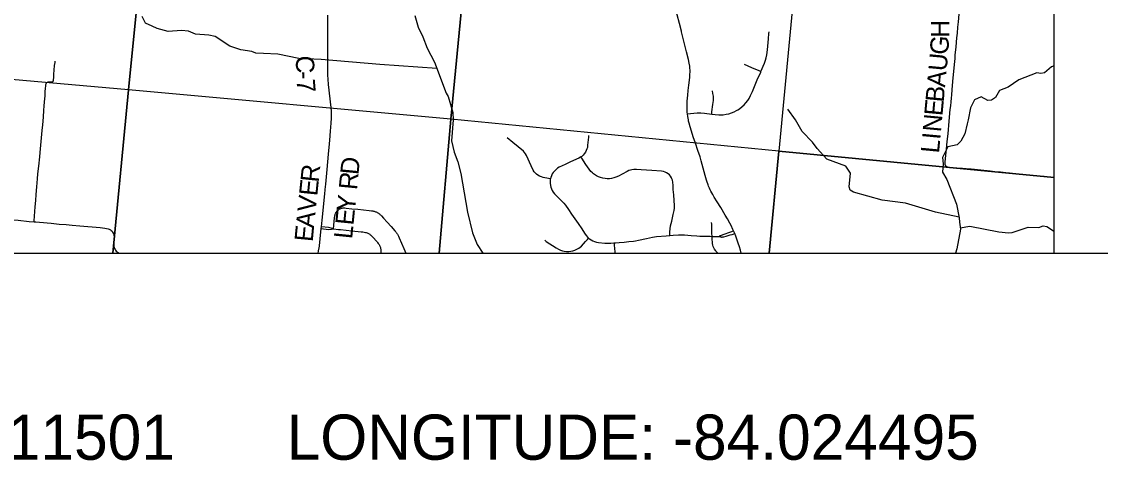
# Model space of a CAD drawing. Extents: x -1.4 to 35.4, y 0 to 22.
# Drawn here: x 28.091 to 31.432, y 12.413 to 13.771 of the extents above; entities that cross this region are included whole.
import ezdxf

# ---------------------------------------------------------------- set-up
doc = ezdxf.new("R2010")
doc.units = 0
for name, color, linetype in [('GM_X_City_Street', 7, 'Continuous'), ('GM_X_County_Road', 7, 'Continuous'), ('GM_X_County_Road_Text', 7, 'Continuous'), ('GM_X_Minor_River', 7, 'Continuous'), ('GM_X_Section', 7, 'Continuous'), ('GM_X_Township_Road', 7, 'Continuous'), ('GM_X_Township_Road_Text', 7, 'Continuous'), ('SC_Scratch1', 7, 'Continuous'), ('SH_Border', 7, 'Continuous'), ('SH_Cut_Line', 7, 'Continuous'), ('SH_Text', 7, 'Continuous')]:
    doc.layers.add(name, color=color, linetype=linetype)

msp = doc.modelspace()

# ---------------------------------------------------------------- linework, layer by layer
at = {"layer": 'GM_X_City_Street'}
msp.add_lwpolyline([(28.1301, 13.1513), (28.1304, 13.1548), (28.1337, 13.1978), (28.135, 13.2176), (28.1364, 13.236), (28.1385, 13.2592), (28.1408, 13.2848), (28.142, 13.2997), (28.1443, 13.3232), (28.1474, 13.3528), (28.1488, 13.3664), (28.1527, 13.411), (28.155, 13.4345), (28.1567, 13.4512), (28.1588, 13.4754), (28.1604, 13.4971), (28.1613, 13.5095), (28.1624, 13.5224), (28.1639, 13.541), (28.1647, 13.5534), (28.1656, 13.565), (28.1661, 13.5711), (28.1668, 13.5767), (28.1671, 13.5782), (28.1675, 13.5794), (28.168, 13.5805), (28.1689, 13.5818), (28.1699, 13.5827), (28.1713, 13.5835), (28.1726, 13.5841), (28.1739, 13.5846), (28.1747, 13.5848), (28.1765, 13.585), (28.1796, 13.5847), (28.1839, 13.5842), (28.1857, 13.5842), (28.1867, 13.5844), (28.1876, 13.5849), (28.1886, 13.586), (28.1893, 13.5874), (28.1897, 13.5887), (28.1902, 13.5924), (28.1907, 13.5973), (28.1914, 13.6104), (28.1919, 13.619), (28.1924, 13.6264), (28.1928, 13.6301), (28.1934, 13.635), (28.195, 13.6448), (28.1957, 13.649)], dxfattribs=at)
at = {"layer": 'GM_X_County_Road'}
for points in [[(31.2897, 13.2886), (31.2897, 14.2937), (30.5317, 14.3711), (30.4366, 13.3703)], [(27.3311, 13.0546), (28.3737, 13.0546), (28.4224, 13.5597), (27.3811, 13.6516)], [(28.3737, 13.0546), (29.3843, 13.0546), (29.4209, 13.4686), (28.4224, 13.5597)], [(29.3843, 13.0546), (30.4062, 13.0546), (30.4366, 13.3703), (29.4209, 13.4686)], [(30.4062, 13.0546), (31.2897, 13.0546), (31.2897, 13.2886), (30.4366, 13.3703)]]:
    msp.add_lwpolyline(points, close=True, dxfattribs=at)
for points in [[(30.1352, 13.7394), (30.1347, 13.7413), (30.1285, 13.7653), (30.1215, 13.7922), (30.1144, 13.8199), (30.1084, 13.8432)], [(29.0125, 13.0701), (29.0136, 13.0773), (29.0161, 13.0983), (29.0192, 13.1304), (29.0197, 13.1362), (29.0219, 13.1564), (29.0273, 13.2065), (29.0307, 13.2392), (29.0318, 13.2491), (29.0319, 13.2509), (29.0335, 13.2676), (29.0376, 13.3128), (29.042, 13.3604), (29.0448, 13.3926), (29.0456, 13.4044), (29.0479, 13.4323), (29.0498, 13.4564), (29.0507, 13.4726), (29.0509, 13.4838), (29.0506, 13.4938), (29.0498, 13.505), (29.0422, 13.5766), (29.0407, 13.5927), (29.04, 13.6057), (29.0396, 13.6212), (29.0399, 13.6535), (29.0399, 13.6777), (29.04, 13.705), (29.04, 13.7473), (29.0401, 13.7908)], [(30.1535, 13.4853), (30.1531, 13.4898), (30.1529, 13.4932), (30.1527, 13.4975), (30.1526, 13.5022), (30.1526, 13.5086), (30.1527, 13.5138), (30.1531, 13.525), (30.1543, 13.543), (30.1557, 13.5575), (30.1576, 13.5741), (30.1604, 13.5986), (30.1609, 13.6042), (30.1612, 13.6091), (30.1614, 13.614), (30.1614, 13.6184), (30.1615, 13.6222), (30.1613, 13.6258), (30.161, 13.6296), (30.1605, 13.6331), (30.159, 13.6422), (30.1563, 13.6543), (30.1506, 13.6778), (30.1434, 13.7061), (30.1352, 13.7394)], [(30.2998, 13.1151), (30.2983, 13.119), (30.2965, 13.1231), (30.2945, 13.1275), (30.2886, 13.1398), (30.2851, 13.147), (30.2772, 13.161), (30.2706, 13.1723), (30.2567, 13.1951), (30.2452, 13.2135), (30.2367, 13.2273), (30.2318, 13.2359), (30.2263, 13.2457), (30.2241, 13.2502), (30.2217, 13.2553), (30.219, 13.2614), (30.2174, 13.2654), (30.2161, 13.2692), (30.2145, 13.2742), (30.2128, 13.2798), (30.2087, 13.2942), (30.2056, 13.3057), (30.1963, 13.3398), (30.1924, 13.3529), (30.1861, 13.3724), (30.1781, 13.3953), (30.1714, 13.414), (30.1656, 13.4317), (30.1614, 13.4454), (30.1584, 13.4569), (30.1571, 13.4624), (30.1562, 13.4672), (30.1545, 13.4771), (30.1535, 13.4853)], [(27.8712, 13.1683), (27.8731, 13.1695), (27.876, 13.1709), (27.8797, 13.172), (27.8835, 13.1727), (27.8867, 13.1729), (27.8917, 13.1727), (27.9177, 13.1707), (27.9258, 13.17), (27.9406, 13.1687), (27.9623, 13.1668), (27.9802, 13.165), (27.9987, 13.1634), (28.0229, 13.1611), (28.0321, 13.1603), (28.0389, 13.1597), (28.0544, 13.1583), (28.0804, 13.1559), (28.1144, 13.1527), (28.1301, 13.1513)], [(28.1301, 13.1513), (28.1354, 13.1509), (28.1701, 13.1478), (28.1824, 13.1467), (28.1991, 13.1452), (28.2072, 13.1445), (28.2294, 13.1425), (28.248, 13.1409), (28.2721, 13.1388), (28.3346, 13.1332), (28.3489, 13.1317), (28.3545, 13.1308), (28.3594, 13.1296), (28.3624, 13.1285), (28.367, 13.1261), (28.3691, 13.1246), (28.3714, 13.1223), (28.3733, 13.1197), (28.3752, 13.1164), (28.3765, 13.1135), (28.3774, 13.1103), (28.3779, 13.1065), (28.3779, 13.1002), (28.3773, 13.0915), (28.3769, 13.0853), (28.3769, 13.0792), (28.3774, 13.0744), (28.3779, 13.072), (28.379, 13.0686), (28.3806, 13.0654), (28.3818, 13.0634), (28.3842, 13.0607), (28.3874, 13.058), (28.3905, 13.0562), (28.3939, 13.0546)], [(30.3197, 13.0546), (30.3174, 13.0633), (30.3143, 13.074), (30.3108, 13.0847), (30.3052, 13.1011), (30.303, 13.1069), (30.2998, 13.1151)], [(29.0094, 13.0546), (29.0109, 13.0607), (29.0122, 13.0681), (29.0125, 13.0701)]]:
    msp.add_lwpolyline(points, dxfattribs=at)
at = {"layer": 'GM_X_Minor_River'}
for points in [[(29.3777, 13.6255), (29.2005, 13.638), (29.0187, 13.6539), (28.9497, 13.6568), (28.8847, 13.6699), (28.84, 13.6727), (28.8165, 13.6731), (28.8041, 13.6783), (28.7704, 13.6836), (28.7358, 13.6953), (28.6908, 13.7246), (28.6708, 13.7289), (28.6299, 13.732), (28.6085, 13.7411), (28.5861, 13.7435), (28.5451, 13.7401), (28.5115, 13.7503), (28.4961, 13.7574), (28.4747, 13.7666), (28.4652, 13.7869)], [(29.3093, 13.7899), (29.3192, 13.754), (29.3338, 13.7238), (29.3475, 13.6886), (29.3702, 13.6452), (29.4066, 13.5492), (29.4121, 13.5396), (29.427, 13.4896), (29.428, 13.4672), (29.423, 13.402), (29.4306, 13.3673), (29.4425, 13.3367), (29.452, 13.3004), (29.472, 13.1808), (29.4874, 13.1175)], [(31.2897, 13.6344), (31.2811, 13.6311), (31.2596, 13.6129), (31.2478, 13.6105), (31.2353, 13.6123), (31.1793, 13.5907), (31.147, 13.5686), (31.1203, 13.5578), (31.1074, 13.5357), (31.0955, 13.5284), (31.0841, 13.5264), (31.0635, 13.5378), (31.0429, 13.5287), (31.0303, 13.504), (31.0224, 13.467), (31.0195, 13.4549), (31.0121, 13.4236), (30.9999, 13.4007), (30.9891, 13.3899), (30.9602, 13.3833), (30.9433, 13.3507), (30.9452, 13.331), (30.9436, 13.3052), (30.9567, 13.2822), (30.9863, 13.2058), (30.9953, 13.1635), (30.9965, 13.1498), (30.9988, 13.1285), (30.9877, 13.0681), (30.9834, 13.0546)], [(30.9948, 13.1658), (30.9218, 13.1813), (30.8285, 13.2094), (30.7568, 13.2188), (30.6676, 13.2434), (30.6571, 13.2493), (30.6539, 13.2593), (30.6585, 13.3024), (30.6438, 13.3232), (30.5852, 13.3449), (30.5556, 13.3781), (30.5408, 13.3981), (30.5085, 13.4314), (30.4884, 13.4667), (30.4641, 13.5005)], [(30.9983, 13.1327), (31.0277, 13.1374), (31.1174, 13.1204), (31.148, 13.1175), (31.159, 13.1184), (31.2086, 13.1348), (31.2418, 13.1341), (31.2552, 13.1391), (31.2665, 13.1366), (31.287, 13.1233), (31.2897, 13.1225)], [(29.4874, 13.1175), (29.5023, 13.0815), (29.5199, 13.0546)]]:
    msp.add_lwpolyline(points, dxfattribs=at)
at = {"layer": 'GM_X_Section'}
for points in [[(28.5233, 14.5759), (28.4224, 13.5597), (27.3811, 13.6516), (27.481, 14.6746)], [(29.5182, 14.475), (29.4209, 13.4686), (28.4224, 13.5597), (28.5233, 14.5759)], [(29.5182, 14.475), (30.5317, 14.3711), (30.4366, 13.3703), (29.4209, 13.4686)]]:
    msp.add_lwpolyline(points, close=True, dxfattribs=at)
at = {"layer": 'GM_X_Township_Road'}
msp.add_line((29.0573, 13.1293), (29.0608, 13.1633), dxfattribs=at)
for points in [[(31.2897, 13.288), (31.2845, 13.2885), (31.2585, 13.2912), (31.24, 13.293), (31.2124, 13.2957), (31.1914, 13.2977), (31.1686, 13.3), (31.1513, 13.3017), (31.1398, 13.3028), (31.1226, 13.3047), (31.1053, 13.3065), (31.0914, 13.3079), (31.0626, 13.3107), (31.0321, 13.3139), (31.0167, 13.3153), (31.0053, 13.3163), (30.9873, 13.3177), (30.9766, 13.3185), (30.9655, 13.3195), (30.9624, 13.3199), (30.9602, 13.3203), (30.9591, 13.3206), (30.9582, 13.3209), (30.9573, 13.3213), (30.9565, 13.3217), (30.9556, 13.3224), (30.9548, 13.3229), (30.9542, 13.3235), (30.9537, 13.3242), (30.9533, 13.3249), (30.9529, 13.3256), (30.9525, 13.3263), (30.9522, 13.3271), (30.952, 13.328), (30.9518, 13.3291), (30.9516, 13.33), (30.9515, 13.3311), (30.9515, 13.3325), (30.9515, 13.3341), (30.9517, 13.3369), (30.9526, 13.3458), (30.9537, 13.3572), (30.9546, 13.3662), (30.9557, 13.3757), (30.9581, 13.4), (30.9605, 13.4242), (30.9643, 13.4631), (30.9674, 13.499), (30.9687, 13.5105), (30.9699, 13.5232), (30.9708, 13.5336), (30.9719, 13.5442), (30.9734, 13.5603), (30.9746, 13.573), (30.9767, 13.5973), (30.9784, 13.6169), (30.9804, 13.6387), (30.9821, 13.6572), (30.9831, 13.6679), (30.9855, 13.6916), (30.9869, 13.7079), (30.9881, 13.7211), (30.9894, 13.7349), (30.9912, 13.754), (30.9929, 13.7701), (30.9955, 13.7943)], [(30.381, 13.6166), (30.3921, 13.6424), (30.3957, 13.6522), (30.3976, 13.6593), (30.3991, 13.6678), (30.4009, 13.6838), (30.4043, 13.7178), (30.4059, 13.7345), (30.4064, 13.7397)], [(30.3288, 13.6395), (30.3522, 13.6291), (30.3744, 13.6195), (30.381, 13.6166)], [(30.2285, 13.4849), (30.239, 13.4836), (30.2507, 13.4826), (30.2581, 13.4826), (30.2636, 13.4827), (30.2733, 13.4843), (30.2817, 13.4861), (30.2899, 13.4887), (30.2985, 13.492), (30.3057, 13.4955), (30.3093, 13.4977), (30.3149, 13.5015), (30.3232, 13.5079), (30.329, 13.5134), (30.3344, 13.5193), (30.34, 13.5266), (30.3444, 13.5333), (30.3491, 13.542), (30.3549, 13.5549), (30.3611, 13.5699), (30.3697, 13.5905), (30.3803, 13.615), (30.381, 13.6166)], [(30.2285, 13.4849), (30.2294, 13.4917), (30.2323, 13.514), (30.2337, 13.5264), (30.234, 13.5344), (30.2338, 13.54), (30.2324, 13.5486), (30.2308, 13.5572)], [(30.1535, 13.4853), (30.1629, 13.4863), (30.1833, 13.4885), (30.1902, 13.4888), (30.1945, 13.4888), (30.2063, 13.4877), (30.2285, 13.4849)], [(29.729, 13.2841), (29.7234, 13.2852), (29.707, 13.2886), (29.7011, 13.2904), (29.6954, 13.2928), (29.69, 13.2959), (29.6855, 13.2992), (29.6819, 13.3026), (29.6787, 13.3064), (29.6757, 13.3111), (29.6692, 13.3245), (29.6549, 13.3569), (29.6521, 13.3617), (29.6492, 13.3657), (29.6453, 13.3697), (29.6127, 13.3965), (29.5954, 13.4109)], [(29.8471, 13.4187), (29.8466, 13.4134), (29.8444, 13.3886), (29.8434, 13.3818), (29.8421, 13.377), (29.8401, 13.3718), (29.8374, 13.3669), (29.8339, 13.3618), (29.8301, 13.3577), (29.826, 13.3539), (29.8233, 13.3521)], [(29.8233, 13.3521), (29.8219, 13.3511), (29.817, 13.3484), (29.7917, 13.3366), (29.7752, 13.3292), (29.7562, 13.32), (29.7514, 13.3171), (29.7464, 13.3134), (29.7424, 13.3095), (29.738, 13.3043), (29.7349, 13.2996), (29.7321, 13.294), (29.73, 13.2882), (29.729, 13.2841)], [(30.0988, 13.1092), (30.0987, 13.1161), (30.0986, 13.1206), (30.0996, 13.1293), (30.1013, 13.1385), (30.1049, 13.1537), (30.1096, 13.1736), (30.1123, 13.1862), (30.1133, 13.1935), (30.1132, 13.2008), (30.1111, 13.2348), (30.1097, 13.2515), (30.1088, 13.2639), (30.1079, 13.2744), (30.1069, 13.2798), (30.1054, 13.2844), (30.1039, 13.2876), (30.101, 13.2922), (30.0975, 13.2964), (30.0935, 13.3001), (30.089, 13.3032), (30.0847, 13.3052), (30.0795, 13.3068), (30.0735, 13.3078), (30.0433, 13.3101), (30.0105, 13.3119), (29.9957, 13.3129), (29.9877, 13.313), (29.9817, 13.3124), (29.9769, 13.3114), (29.9723, 13.3099), (29.9663, 13.307), (29.9511, 13.2984), (29.9395, 13.2925), (29.932, 13.2892), (29.9254, 13.2871), (29.9187, 13.2855), (29.9124, 13.2848), (29.9048, 13.2846), (29.8986, 13.2851), (29.8911, 13.2864), (29.8845, 13.2883), (29.878, 13.2908), (29.8718, 13.2939), (29.8628, 13.2996), (29.8589, 13.3028), (29.8545, 13.3074), (29.849, 13.3142), (29.8391, 13.3286), (29.826, 13.3481), (29.8233, 13.3521)], [(29.729, 13.2841), (29.7287, 13.2828), (29.728, 13.2772), (29.7281, 13.271), (29.7289, 13.2642), (29.7303, 13.2582), (29.7322, 13.2529), (29.7347, 13.2479), (29.7377, 13.2432), (29.7416, 13.2384), (29.7525, 13.2273), (29.7709, 13.2088), (29.7759, 13.2025), (29.7852, 13.1893), (29.7946, 13.1754), (29.8149, 13.1456), (29.8261, 13.1292), (29.8351, 13.1158), (29.8402, 13.1088), (29.8451, 13.1032), (29.8474, 13.1011)], [(29.0608, 13.1633), (29.0614, 13.1689), (29.0617, 13.1705), (29.062, 13.1722), (29.0624, 13.1738), (29.0629, 13.1753), (29.0635, 13.1769), (29.0641, 13.1784), (29.0649, 13.1799), (29.0658, 13.1813), (29.0667, 13.1826), (29.0677, 13.1839), (29.0688, 13.1852), (29.0699, 13.1864), (29.0712, 13.1875), (29.0724, 13.1885), (29.0738, 13.1895), (29.0752, 13.1904), (29.0766, 13.1912), (29.0781, 13.1919), (29.0796, 13.1925), (29.0812, 13.1931), (29.0828, 13.1935), (29.0844, 13.1939), (29.086, 13.1941), (29.0877, 13.1943), (29.0893, 13.1944), (29.091, 13.1943), (29.0926, 13.1942), (29.0964, 13.1938), (29.1143, 13.1919), (29.1322, 13.1901), (29.1501, 13.1882), (29.168, 13.1863), (29.1751, 13.1856), (29.1772, 13.1853), (29.1793, 13.185), (29.1813, 13.1845), (29.1833, 13.184), (29.1853, 13.1834), (29.1873, 13.1826), (29.1892, 13.1819), (29.1911, 13.181), (29.193, 13.18), (29.1947, 13.179), (29.1964, 13.1779), (29.1981, 13.1768), (29.1997, 13.1756), (29.2012, 13.1743), (29.2027, 13.1729), (29.2041, 13.1715), (29.2055, 13.17), (29.2117, 13.1631), (29.2237, 13.1497), (29.2357, 13.1363), (29.2476, 13.1229), (29.2483, 13.1221), (29.2498, 13.1204), (29.2512, 13.1186), (29.2526, 13.1168), (29.2538, 13.1149), (29.255, 13.113), (29.2561, 13.111), (29.2572, 13.1089), (29.2581, 13.1069), (29.2602, 13.1019), (29.2674, 13.0854), (29.2746, 13.0689), (29.2808, 13.0546)], [(29.0573, 13.1293), (29.0503, 13.1321), (29.042, 13.1338), (29.0197, 13.1362)], [(30.2299, 13.1062), (30.2294, 13.1161), (30.2287, 13.1351), (30.2286, 13.1435), (30.2283, 13.1493)], [(29.0192, 13.1304), (29.0418, 13.128), (29.0514, 13.1284), (29.0573, 13.1293)], [(29.0573, 13.1293), (29.0727, 13.1277), (29.0789, 13.1271), (29.1138, 13.1235), (29.1434, 13.1204), (29.1481, 13.1199), (29.1524, 13.1194), (29.1561, 13.1187), (29.1587, 13.118), (29.1612, 13.1172), (29.1633, 13.1163), (29.1656, 13.1152), (29.1678, 13.1138), (29.1694, 13.1128), (29.1712, 13.1114), (29.1731, 13.1098), (29.175, 13.1079), (29.1777, 13.1049), (29.192, 13.089), (29.1939, 13.0868), (29.1959, 13.0844), (29.1971, 13.0828), (29.1983, 13.081), (29.1993, 13.0793), (29.2001, 13.0779), (29.2012, 13.0754), (29.2019, 13.0737), (29.2024, 13.0719), (29.2029, 13.0701), (29.2033, 13.0683), (29.2036, 13.0665), (29.2038, 13.0647), (29.204, 13.0629), (29.204, 13.061), (29.204, 13.0592), (29.2037, 13.056), (29.2036, 13.0546)], [(29.7114, 13.094), (29.7162, 13.0907), (29.7465, 13.0711), (29.7545, 13.0664), (29.7601, 13.0637), (29.766, 13.0618), (29.7721, 13.0604), (29.7789, 13.0596), (29.7857, 13.0595), (29.7925, 13.06), (29.7986, 13.0613), (29.8045, 13.0632), (29.8113, 13.0662), (29.8167, 13.0692), (29.8212, 13.0725), (29.8253, 13.0763), (29.8377, 13.0903), (29.8435, 13.0967), (29.8474, 13.1011)], [(29.8474, 13.1011), (29.8497, 13.099), (29.8548, 13.0955), (29.8602, 13.0925), (29.866, 13.0902), (29.8714, 13.0887), (29.8775, 13.0876), (29.8973, 13.0857), (29.9072, 13.0853), (29.9159, 13.0854), (29.9258, 13.0861)], [(29.9258, 13.0861), (29.9308, 13.0864), (29.9419, 13.0874), (29.9574, 13.0887), (29.9722, 13.0901), (29.9864, 13.0915), (29.9925, 13.0924), (30.0023, 13.0943), (30.0265, 13.0998), (30.0453, 13.1039), (30.0576, 13.1057), (30.0873, 13.1083), (30.0988, 13.1092)], [(30.0988, 13.1092), (30.109, 13.11), (30.1257, 13.1109), (30.1444, 13.1108), (30.1549, 13.1104), (30.1654, 13.1092), (30.1827, 13.1074), (30.1919, 13.1071), (30.2006, 13.107), (30.211, 13.107), (30.2177, 13.107), (30.2239, 13.1066), (30.2299, 13.1062)], [(30.2299, 13.1062), (30.2327, 13.1061), (30.2476, 13.1056), (30.2518, 13.1056)], [(30.2471, 13.0546), (30.2456, 13.0558), (30.244, 13.0574), (30.2426, 13.0592), (30.2413, 13.061), (30.2371, 13.0671), (30.235, 13.0709), (30.2332, 13.0749), (30.232, 13.0791), (30.2312, 13.0846), (30.2303, 13.1002), (30.2299, 13.1062)], [(30.2518, 13.1056), (30.2532, 13.1071), (30.2541, 13.108), (30.2548, 13.1085), (30.2554, 13.1089), (30.2564, 13.1094), (30.2641, 13.1119), (30.288, 13.1202), (30.2965, 13.1231)], [(30.2518, 13.1056), (30.2558, 13.1047), (30.2574, 13.1044), (30.2591, 13.1042), (30.2608, 13.1042), (30.2628, 13.1043), (30.2642, 13.1046), (30.2658, 13.1049), (30.2731, 13.1068), (30.2862, 13.1109), (30.2915, 13.1125), (30.2998, 13.1151)], [(29.9258, 13.0861), (29.9261, 13.0817), (29.9263, 13.0786), (29.9282, 13.0588), (29.9283, 13.0546)]]:
    msp.add_lwpolyline(points, dxfattribs=at)
at = {"layer": 'SC_Scratch1'}
msp.add_line((-1.4282, 13.0546), (35.3749, 13.0546), dxfattribs=at)
msp.add_lwpolyline([(24.4897, 13.0546), (31.2897, 13.0546), (31.2897, 14.2945), (31.0327, 14.3243), (30.5349, 14.3735), (30.078, 14.4186), (29.219, 14.5015), (29.0246, 14.529), (28.654, 14.5669), (28.5833, 14.5741), (28.5412, 14.5785), (28.5208, 14.5804), (27.9039, 14.6378)], dxfattribs=at)
at = {"layer": 'SH_Border'}
msp.add_lwpolyline([(24.4897, 19.8546), (24.4921, 13.0546), (31.2897, 13.0546), (31.2897, 19.8546)], close=True, dxfattribs=at)
at = {"layer": 'SH_Cut_Line'}
msp.add_lwpolyline([(24.4897, 13.0546), (31.2897, 13.0546), (31.2897, 19.3549)], dxfattribs=at)

# ---------------------------------------------------------------- texts
at = {"layer": 'GM_X_County_Road_Text'}
for s, rotation, p in [('C', 270.3318, (28.9409, 13.6657)), ('-', 272.3364, (28.9412, 13.6169)), ('7', 274.7736, (28.9424, 13.591)), ('D', 84.3689, (29.1344, 13.295)), ('R', 84.1783, (29.0112, 13.2719)), ('R', 84.3667, (29.1298, 13.2486)), ('E', 84.1785, (29.0068, 13.2296)), ('V', 84.1789, (29.0018, 13.1799)), ('Y', 84.366, (29.1232, 13.1814)), ('A', 84.1759, (28.9967, 13.1301)), ('E', 84.3535, (29.119, 13.1391)), ('E', 84.5977, (28.9927, 13.0879)), ('L', 84.2905, (29.1148, 13.0967))]:
    msp.add_text(s, height=0.0568, rotation=rotation, dxfattribs=at).set_placement(p)
at = {"layer": 'GM_X_Township_Road_Text'}
for s, rotation, p in [('H', 90.0281, (30.9642, 13.7214)), ('G', 85.952, (30.9605, 13.6672)), ('U', 84.7327, (30.9558, 13.6161)), ('A', 84.7215, (30.9512, 13.5663)), ('B', 84.7197, (30.9469, 13.5198)), ('E', 84.7238, (30.943, 13.4775)), ('N', 84.7215, (30.9384, 13.4277)), ('L', 84.7214, (30.9324, 13.3621)), ('I', 84.7221, (30.9363, 13.4044))]:
    msp.add_text(s, height=0.0568, rotation=rotation, dxfattribs=at).set_placement(p)
at = {"layer": 'SH_Text'}
for s, p in [('LATITUDE: 39.811501', (26.6721, 12.4146)), ('LONGITUDE: -84.024495', (28.9121, 12.4146))]:
    msp.add_text(s, height=0.14, dxfattribs=at).set_placement(p)

doc.saveas('drawing.dxf')
